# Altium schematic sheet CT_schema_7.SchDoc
size 277 x 170 mm
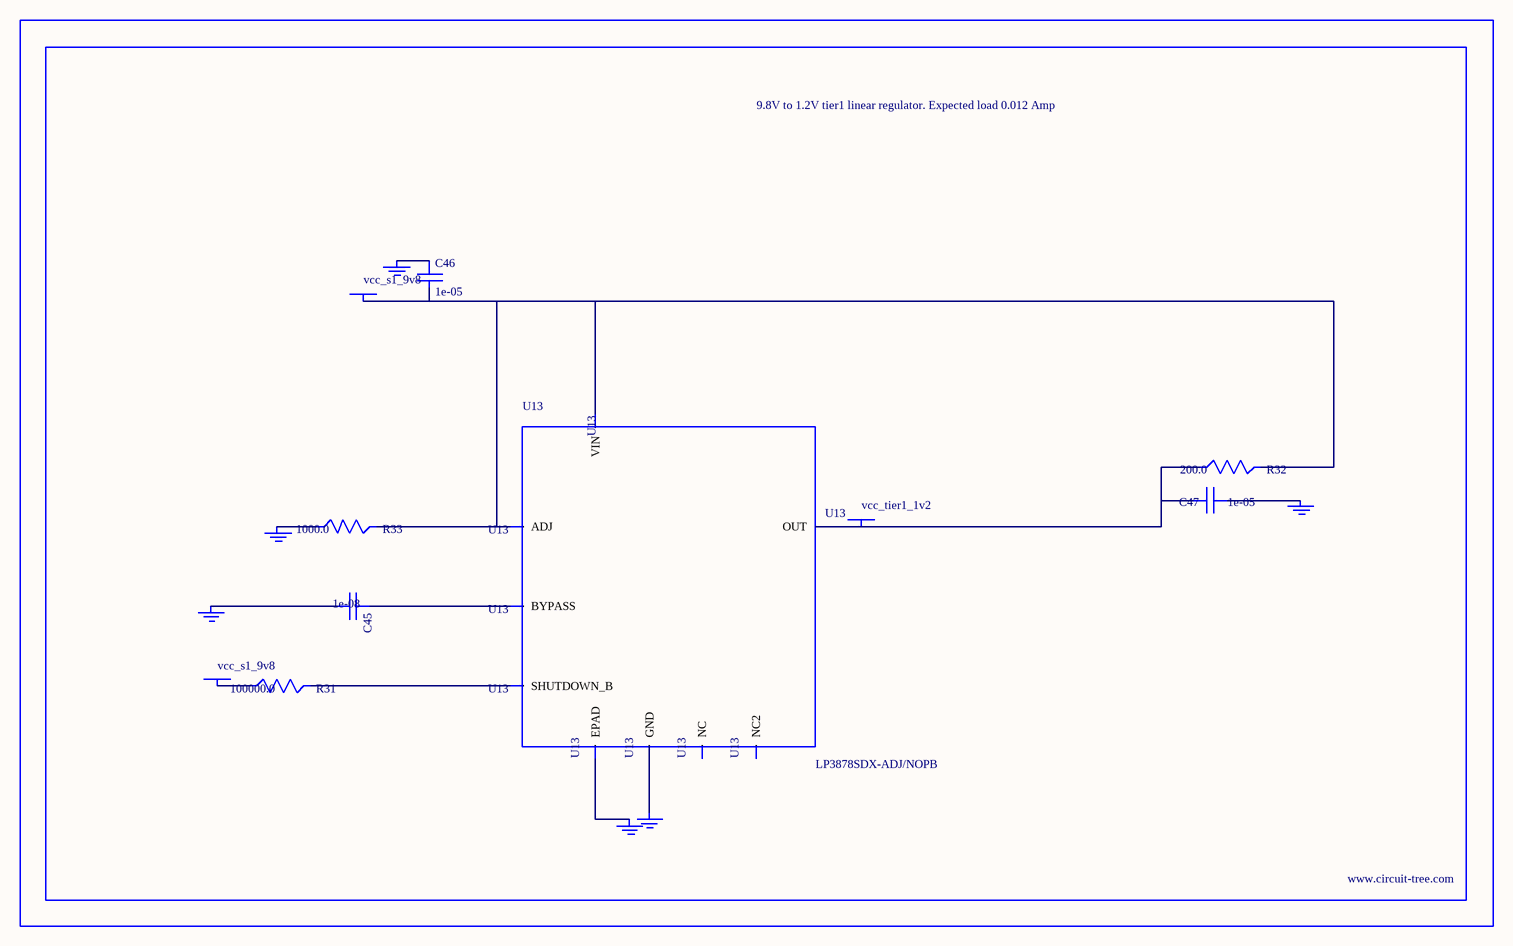
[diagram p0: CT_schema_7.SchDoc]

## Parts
BORDER6  (no value)
C45  1e-08  [C0402]
C46  1e-05  [C1206]
C47  1e-05  [C0805]
GND_INSTANCE_6_0  (no value)
GND_INSTANCE_6_1  (no value)
GND_INSTANCE_6_2  (no value)
GND_INSTANCE_6_3  (no value)
GND_INSTANCE_6_4  (no value)
GND_INSTANCE_6_5  (no value)
POWER_INSTANCE_6_0  vcc_s1_9v8
POWER_INSTANCE_6_1  vcc_s1_9v8
POWER_INSTANCE_6_2  vcc_tier1_1v2
R31  100000.0  [R0603]
R32  200.0  [R0603]
R33  1000.0  [R0603]
U13  LP3878SDX-ADJ/NOPB  [WSON-8]

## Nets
NetC45_1: C45.1 U13.1(BYPASS)
NetC45_2: C45.2 GND_INSTANCE_6_0.0(GND)
NetC46_1: C46.1 GND_INSTANCE_6_1.0(GND)
NetC46_2: C46.2 POWER_INSTANCE_6_0.0(PWR) R32.2 R33.2 U13.4(VIN) U13.6(ADJ)
NetC47_1: C47.1 GND_INSTANCE_6_2.0(GND)
NetC47_2: C47.2 POWER_INSTANCE_6_2.0(PWR) R32.1 U13.5(OUT)
NetGND_INSTANCE_6_3_0: GND_INSTANCE_6_3.0(GND) R33.1
NetGND_INSTANCE_6_4_0: GND_INSTANCE_6_4.0(GND) U13.PAD(EPAD)
NetGND_INSTANCE_6_5_0: GND_INSTANCE_6_5.0(GND) U13.3(GND)
NetPOWER_INSTANCE_6_1_0: POWER_INSTANCE_6_1.0(PWR) R31.1
NetR31_2: R31.2 U13.8(SHUTDOWN_B)

Not connected (* = marked no-connect by the designer): U13 2(NC) 7(NC2)

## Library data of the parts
BORDER6 = BORDER_PAGE6
C45 = C0402C103K3RAC
C46 = C1206C106K3RACTU
C47 = GRM219R60J106ME19D
GND_INSTANCE_6_0-GND_INSTANCE_6_5 = GND
POWER_INSTANCE_6_0-POWER_INSTANCE_6_2 = PWR
R31 = RC0603JR-07100KL
R32 = RC0603JR-07200RL
R33 = RC0603JR-071KL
